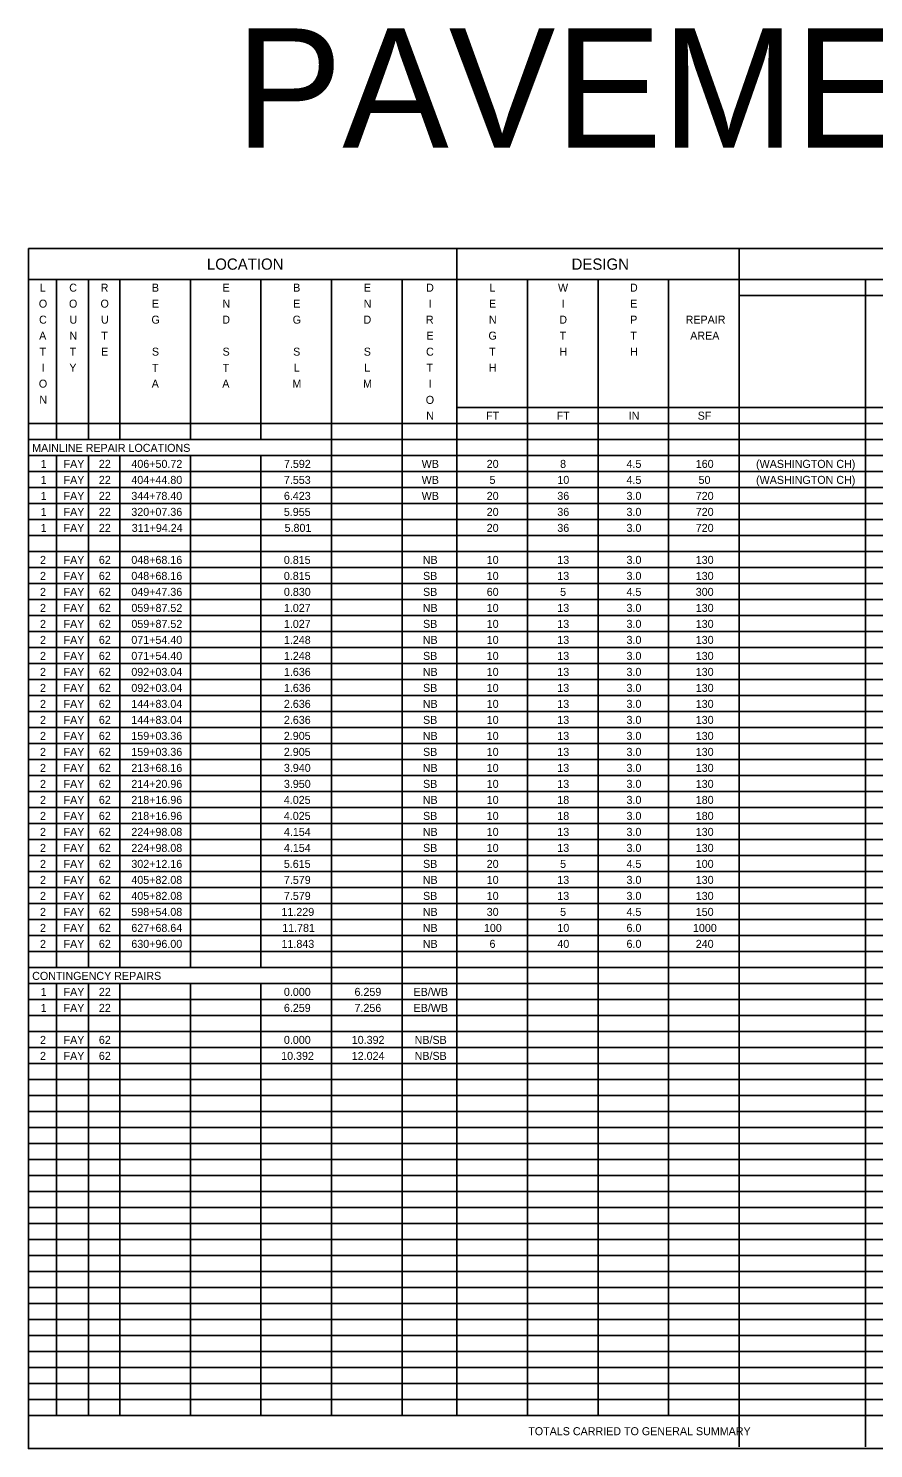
# Model space of a CAD drawing. Extents: x 12522 to 13018, y 1124 to 1902.
# Drawn here: x 12797.22 to 12812.01, y 1864.19 to 1889.04 of the extents above; entities that cross this region are included whole.
import ezdxf

# ---------------------------------------------------------------- set-up
doc = ezdxf.new("R2010")
doc.units = 0
for name, color, linetype in [('SC_Scratch1', 7, 'Continuous'), ('SH_Data', 7, 'Continuous'), ('SH_Text', 7, 'Continuous')]:
    doc.layers.add(name, color=color, linetype=linetype)

msp = doc.modelspace()

# ---------------------------------------------------------------- linework, layer by layer
at = {"layer": 'SC_Scratch1'}
msp.add_lwpolyline([(12797.224, 1885.19), (12827.724, 1885.19), (12827.724, 1864.19), (12797.224, 1864.19)], close=True, dxfattribs=at)
at = {"layer": 'SH_Data'}
for p, q in [((12804.718, 1885.19), (12804.718, 1864.766)), ((12809.659, 1885.19), (12809.659, 1864.223)), ((12797.224, 1884.646), (12827.728, 1884.646)), ((12797.718, 1884.646), (12797.718, 1881.846)), ((12798.278, 1884.646), (12798.278, 1881.846)), ((12798.822, 1884.646), (12798.822, 1881.846)), ((12800.057, 1884.646), (12800.057, 1881.846)), ((12801.292, 1884.646), (12801.292, 1881.846)), ((12802.528, 1884.646), (12802.528, 1864.766)), ((12803.763, 1884.646), (12803.763, 1864.766)), ((12805.954, 1884.646), (12805.954, 1864.766)), ((12807.189, 1884.646), (12807.189, 1864.766)), ((12808.424, 1884.646), (12808.424, 1864.766)), ((12811.867, 1884.646), (12811.867, 1864.223)), ((12809.659, 1884.366), (12820.695, 1884.366)), ((12804.718, 1882.406), (12820.695, 1882.406)), ((12797.224, 1882.126), (12827.728, 1882.126)), ((12797.224, 1881.846), (12827.728, 1881.846)), ((12797.224, 1881.566), (12827.728, 1881.566)), ((12797.718, 1881.566), (12797.718, 1872.606)), ((12798.278, 1881.566), (12798.278, 1872.606)), ((12798.822, 1881.566), (12798.822, 1872.606)), ((12800.057, 1881.566), (12800.057, 1872.606)), ((12801.292, 1881.566), (12801.292, 1872.606)), ((12797.224, 1881.286), (12827.728, 1881.286)), ((12797.224, 1881.006), (12827.728, 1881.006)), ((12797.224, 1880.726), (12827.728, 1880.726)), ((12797.224, 1880.446), (12827.728, 1880.446)), ((12797.224, 1880.166), (12827.728, 1880.166)), ((12797.224, 1879.886), (12827.728, 1879.886)), ((12797.224, 1879.606), (12827.728, 1879.606)), ((12797.224, 1879.326), (12827.728, 1879.326)), ((12797.224, 1879.046), (12827.728, 1879.046)), ((12797.224, 1878.766), (12827.728, 1878.766)), ((12797.224, 1878.486), (12827.728, 1878.486)), ((12797.224, 1878.206), (12827.728, 1878.206)), ((12797.224, 1877.926), (12827.728, 1877.926)), ((12797.224, 1877.646), (12827.728, 1877.646)), ((12797.224, 1877.366), (12827.728, 1877.366)), ((12797.224, 1877.086), (12827.728, 1877.086)), ((12797.224, 1876.806), (12827.728, 1876.806)), ((12797.224, 1876.526), (12827.728, 1876.526)), ((12797.224, 1876.246), (12827.728, 1876.246)), ((12797.224, 1875.966), (12827.728, 1875.966)), ((12797.224, 1875.686), (12827.728, 1875.686)), ((12797.224, 1875.406), (12827.728, 1875.406)), ((12797.224, 1875.126), (12827.728, 1875.126)), ((12797.224, 1874.846), (12827.728, 1874.846)), ((12797.224, 1874.566), (12827.728, 1874.566)), ((12797.224, 1874.286), (12827.728, 1874.286)), ((12797.224, 1874.006), (12827.728, 1874.006)), ((12797.224, 1873.726), (12827.728, 1873.726)), ((12797.224, 1873.446), (12827.728, 1873.446)), ((12797.224, 1873.166), (12827.728, 1873.166)), ((12797.224, 1872.886), (12827.728, 1872.886)), ((12797.224, 1872.606), (12827.728, 1872.606)), ((12797.224, 1872.326), (12827.728, 1872.326)), ((12797.718, 1872.326), (12797.718, 1864.766)), ((12798.278, 1872.326), (12798.278, 1864.766)), ((12798.822, 1872.326), (12798.822, 1864.766)), ((12800.057, 1872.326), (12800.057, 1864.766)), ((12801.292, 1872.326), (12801.292, 1864.766)), ((12797.224, 1872.046), (12827.728, 1872.046)), ((12797.224, 1871.766), (12827.728, 1871.766)), ((12797.224, 1871.486), (12827.728, 1871.486)), ((12797.224, 1871.206), (12827.728, 1871.206)), ((12797.224, 1870.926), (12827.728, 1870.926)), ((12797.224, 1870.646), (12827.728, 1870.646)), ((12797.224, 1870.366), (12827.728, 1870.366)), ((12797.224, 1870.086), (12827.728, 1870.086)), ((12797.224, 1869.806), (12827.728, 1869.806)), ((12797.224, 1869.526), (12827.728, 1869.526)), ((12797.224, 1869.246), (12827.728, 1869.246)), ((12797.224, 1868.966), (12827.728, 1868.966)), ((12797.224, 1868.686), (12827.728, 1868.686)), ((12797.224, 1868.406), (12827.728, 1868.406)), ((12797.224, 1868.126), (12827.728, 1868.126)), ((12797.224, 1867.846), (12827.728, 1867.846)), ((12797.224, 1867.566), (12827.728, 1867.566)), ((12797.224, 1867.286), (12827.728, 1867.286)), ((12797.224, 1867.006), (12827.728, 1867.006)), ((12797.224, 1866.726), (12827.728, 1866.726)), ((12797.224, 1866.446), (12827.728, 1866.446)), ((12797.224, 1866.166), (12827.728, 1866.166)), ((12797.224, 1865.886), (12827.728, 1865.886)), ((12797.224, 1865.606), (12827.728, 1865.606)), ((12797.224, 1865.326), (12827.728, 1865.326)), ((12797.224, 1865.046), (12827.728, 1865.046)), ((12797.224, 1864.766), (12827.728, 1864.766))]:
    msp.add_line(p, q, dxfattribs=at)

# ---------------------------------------------------------------- texts
at = {"layer": 'SC_Scratch1'}
msp.add_text('PAVEMENT REPAIR', height=2.08957, dxfattribs=at).set_placement((12800.851, 1886.953))
at = {"layer": 'SH_Text'}
for s, height, p in [('LOCATION', 0.196, (12800.347, 1884.82)), ('DESIGN', 0.196, (12806.726, 1884.82)), ('L', 0.14, (12797.425, 1884.436)), ('C', 0.14, (12797.938, 1884.436)), ('R', 0.14, (12798.488, 1884.436)), ('B', 0.14, (12799.385, 1884.436)), ('E', 0.14, (12800.621, 1884.436)), ('B', 0.14, (12801.856, 1884.436)), ('E', 0.14, (12803.091, 1884.436)), ('D', 0.14, (12804.182, 1884.436)), ('L', 0.14, (12805.29, 1884.436)), ('W', 0.14, (12806.489, 1884.436)), ('D', 0.14, (12807.748, 1884.436)), ('O', 0.14, (12797.407, 1884.156)), ('O', 0.14, (12797.934, 1884.156)), ('O', 0.14, (12798.486, 1884.156)), ('E', 0.14, (12799.385, 1884.156)), ('N', 0.14, (12800.618, 1884.156)), ('E', 0.14, (12801.856, 1884.156)), ('N', 0.14, (12803.089, 1884.156)), ('I', 0.14, (12804.224, 1884.156)), ('E', 0.14, (12805.282, 1884.156)), ('I', 0.14, (12806.555, 1884.156)), ('E', 0.14, (12807.753, 1884.156)), ('C', 0.14, (12797.411, 1883.876)), ('U', 0.14, (12797.942, 1883.876)), ('U', 0.14, (12798.494, 1883.876)), ('G', 0.14, (12799.377, 1883.876)), ('D', 0.14, (12800.616, 1883.876)), ('G', 0.14, (12801.847, 1883.876)), ('D', 0.14, (12803.087, 1883.876)), ('R', 0.14, (12804.178, 1883.876)), ('N', 0.14, (12805.28, 1883.876)), ('D', 0.14, (12806.512, 1883.876)), ('P', 0.14, (12807.752, 1883.876)), ('REPAIR', 0.14, (12808.722, 1883.876)), ('A', 0.14, (12797.412, 1883.596)), ('N', 0.14, (12797.942, 1883.596)), ('T', 0.14, (12798.498, 1883.596)), ('E', 0.14, (12804.187, 1883.596)), ('G', 0.14, (12805.273, 1883.596)), ('T', 0.14, (12806.519, 1883.596)), ('T', 0.14, (12807.755, 1883.596)), ('AREA', 0.14, (12808.802, 1883.596)), ('T', 0.14, (12797.419, 1883.316)), ('T', 0.14, (12797.946, 1883.316)), ('E', 0.14, (12798.496, 1883.316)), ('S', 0.14, (12799.385, 1883.316)), ('S', 0.14, (12800.621, 1883.316)), ('S', 0.14, (12801.856, 1883.316)), ('S', 0.14, (12803.091, 1883.316)), ('C', 0.14, (12804.181, 1883.316)), ('T', 0.14, (12805.284, 1883.316)), ('H', 0.14, (12806.515, 1883.316)), ('H', 0.14, (12807.75, 1883.316)), ('I', 0.14, (12797.455, 1883.036)), ('Y', 0.14, (12797.94, 1883.036)), ('T', 0.14, (12799.387, 1883.032)), ('T', 0.14, (12800.623, 1883.032)), ('L', 0.14, (12801.864, 1883.036)), ('L', 0.14, (12803.1, 1883.036)), ('T', 0.14, (12804.189, 1883.036)), ('H', 0.14, (12805.279, 1883.036)), ('O', 0.14, (12797.407, 1882.756)), ('A', 0.14, (12799.381, 1882.756)), ('A', 0.14, (12800.616, 1882.756)), ('M', 0.14, (12801.843, 1882.756)), ('M', 0.14, (12803.079, 1882.756)), ('I', 0.14, (12804.224, 1882.756)), ('N', 0.14, (12797.415, 1882.476)), ('O', 0.14, (12804.176, 1882.472)), ('N', 0.14, (12804.184, 1882.196)), ('FT', 0.14, (12805.23, 1882.196)), ('FT', 0.14, (12806.465, 1882.196)), ('IN', 0.14, (12807.726, 1882.196)), ('SF', 0.14, (12808.933, 1882.196)), ('MAINLINE REPAIR LOCATIONS', 0.14, (12797.29, 1881.632)), ('1', 0.14, (12797.439, 1881.352)), ('FAY', 0.14, (12797.839, 1881.352)), ('22', 0.14, (12798.457, 1881.352)), ('406+50.72', 0.14, (12799.026, 1881.352)), ('7.592', 0.14, (12801.695, 1881.352)), ('WB', 0.14, (12804.104, 1881.352)), ('20', 0.14, (12805.242, 1881.352)), ('8', 0.14, (12806.526, 1881.352)), ('4.5', 0.14, (12807.688, 1881.352)), ('160', 0.14, (12808.899, 1881.352)), ('(WASHINGTON CH)', 0.14, (12809.954, 1881.352)), ('1', 0.14, (12797.439, 1881.072)), ('FAY', 0.14, (12797.839, 1881.072)), ('22', 0.14, (12798.457, 1881.072)), ('404+44.80', 0.14, (12799.025, 1881.072)), ('7.553', 0.14, (12801.694, 1881.072)), ('WB', 0.14, (12804.104, 1881.072)), ('5', 0.14, (12805.291, 1881.072)), ('10', 0.14, (12806.478, 1881.072)), ('4.5', 0.14, (12807.688, 1881.072)), ('50', 0.14, (12808.948, 1881.072)), ('(WASHINGTON CH)', 0.14, (12809.954, 1881.072)), ('1', 0.14, (12797.439, 1880.792)), ('FAY', 0.14, (12797.839, 1880.792)), ('22', 0.14, (12798.457, 1880.792)), ('344+78.40', 0.14, (12799.025, 1880.792)), ('6.423', 0.14, (12801.694, 1880.792)), ('WB', 0.14, (12804.104, 1880.792)), ('20', 0.14, (12805.242, 1880.792)), ('36', 0.14, (12806.477, 1880.792)), ('3.0', 0.14, (12807.688, 1880.792)), ('720', 0.14, (12808.899, 1880.792)), ('1', 0.14, (12797.439, 1880.512)), ('FAY', 0.14, (12797.839, 1880.512)), ('22', 0.14, (12798.457, 1880.512)), ('320+07.36', 0.14, (12799.025, 1880.512)), ('5.955', 0.14, (12801.693, 1880.512)), ('20', 0.14, (12805.242, 1880.512)), ('36', 0.14, (12806.477, 1880.512)), ('3.0', 0.14, (12807.688, 1880.512)), ('720', 0.14, (12808.899, 1880.512)), ('1', 0.14, (12797.439, 1880.232)), ('FAY', 0.14, (12797.839, 1880.232)), ('22', 0.14, (12798.457, 1880.232)), ('311+94.24', 0.14, (12799.032, 1880.232)), ('5.801', 0.14, (12801.706, 1880.232)), ('20', 0.14, (12805.242, 1880.232)), ('36', 0.14, (12806.477, 1880.232)), ('3.0', 0.14, (12807.688, 1880.232)), ('720', 0.14, (12808.899, 1880.232)), ('2', 0.14, (12797.427, 1879.672)), ('FAY', 0.14, (12797.839, 1879.672)), ('62', 0.14, (12798.457, 1879.672)), ('048+68.16', 0.14, (12799.025, 1879.672)), ('0.815', 0.14, (12801.693, 1879.672)), ('NB', 0.14, (12804.123, 1879.672)), ('10', 0.14, (12805.242, 1879.672)), ('13', 0.14, (12806.477, 1879.672)), ('3.0', 0.14, (12807.688, 1879.672)), ('130', 0.14, (12808.899, 1879.672)), ('2', 0.14, (12797.427, 1879.392)), ('FAY', 0.14, (12797.839, 1879.392)), ('62', 0.14, (12798.457, 1879.392)), ('048+68.16', 0.14, (12799.025, 1879.392)), ('0.815', 0.14, (12801.693, 1879.392)), ('SB', 0.14, (12804.128, 1879.392)), ('10', 0.14, (12805.242, 1879.392)), ('13', 0.14, (12806.477, 1879.392)), ('3.0', 0.14, (12807.688, 1879.392)), ('130', 0.14, (12808.899, 1879.392)), ('2', 0.14, (12797.427, 1879.112)), ('FAY', 0.14, (12797.839, 1879.112)), ('62', 0.14, (12798.457, 1879.112)), ('049+47.36', 0.14, (12799.025, 1879.112)), ('0.830', 0.14, (12801.694, 1879.112)), ('SB', 0.14, (12804.128, 1879.112)), ('60', 0.14, (12805.242, 1879.112)), ('5', 0.14, (12806.526, 1879.112)), ('4.5', 0.14, (12807.688, 1879.112)), ('300', 0.14, (12808.899, 1879.112)), ('2', 0.14, (12797.427, 1878.832)), ('FAY', 0.14, (12797.839, 1878.832)), ('62', 0.14, (12798.457, 1878.832)), ('059+87.52', 0.14, (12799.026, 1878.832)), ('1.027', 0.14, (12801.694, 1878.832)), ('NB', 0.14, (12804.123, 1878.832)), ('10', 0.14, (12805.242, 1878.832)), ('13', 0.14, (12806.477, 1878.832)), ('3.0', 0.14, (12807.688, 1878.832)), ('130', 0.14, (12808.899, 1878.832)), ('2', 0.14, (12797.427, 1878.552)), ('FAY', 0.14, (12797.839, 1878.552)), ('62', 0.14, (12798.457, 1878.552)), ('059+87.52', 0.14, (12799.026, 1878.552)), ('1.027', 0.14, (12801.694, 1878.552)), ('SB', 0.14, (12804.128, 1878.552)), ('10', 0.14, (12805.242, 1878.552)), ('13', 0.14, (12806.477, 1878.552)), ('3.0', 0.14, (12807.688, 1878.552)), ('130', 0.14, (12808.899, 1878.552)), ('2', 0.14, (12797.427, 1878.272)), ('FAY', 0.14, (12797.839, 1878.272)), ('62', 0.14, (12798.457, 1878.272)), ('071+54.40', 0.14, (12799.025, 1878.272)), ('1.248', 0.14, (12801.694, 1878.272)), ('NB', 0.14, (12804.123, 1878.272)), ('10', 0.14, (12805.242, 1878.272)), ('13', 0.14, (12806.477, 1878.272)), ('3.0', 0.14, (12807.688, 1878.272)), ('130', 0.14, (12808.899, 1878.272)), ('2', 0.14, (12797.427, 1877.992)), ('FAY', 0.14, (12797.839, 1877.992)), ('62', 0.14, (12798.457, 1877.992)), ('071+54.40', 0.14, (12799.025, 1877.992)), ('1.248', 0.14, (12801.694, 1877.992)), ('SB', 0.14, (12804.128, 1877.992)), ('10', 0.14, (12805.242, 1877.992)), ('13', 0.14, (12806.477, 1877.992)), ('3.0', 0.14, (12807.688, 1877.992)), ('130', 0.14, (12808.899, 1877.992)), ('2', 0.14, (12797.427, 1877.712)), ('FAY', 0.14, (12797.839, 1877.712)), ('62', 0.14, (12798.457, 1877.712)), ('092+03.04', 0.14, (12799.025, 1877.712)), ('1.636', 0.14, (12801.694, 1877.712)), ('NB', 0.14, (12804.123, 1877.712)), ('10', 0.14, (12805.242, 1877.712)), ('13', 0.14, (12806.477, 1877.712)), ('3.0', 0.14, (12807.688, 1877.712)), ('130', 0.14, (12808.899, 1877.712)), ('2', 0.14, (12797.427, 1877.432)), ('FAY', 0.14, (12797.839, 1877.432)), ('62', 0.14, (12798.457, 1877.432)), ('092+03.04', 0.14, (12799.025, 1877.432)), ('1.636', 0.14, (12801.694, 1877.432)), ('SB', 0.14, (12804.128, 1877.432)), ('10', 0.14, (12805.242, 1877.432)), ('13', 0.14, (12806.477, 1877.432)), ('3.0', 0.14, (12807.688, 1877.432)), ('130', 0.14, (12808.899, 1877.432)), ('2', 0.14, (12797.427, 1877.152)), ('FAY', 0.14, (12797.839, 1877.152)), ('62', 0.14, (12798.457, 1877.152)), ('144+83.04', 0.14, (12799.025, 1877.152)), ('2.636', 0.14, (12801.694, 1877.152)), ('NB', 0.14, (12804.123, 1877.152)), ('10', 0.14, (12805.242, 1877.152)), ('13', 0.14, (12806.477, 1877.152)), ('3.0', 0.14, (12807.688, 1877.152)), ('130', 0.14, (12808.899, 1877.152)), ('2', 0.14, (12797.427, 1876.872)), ('FAY', 0.14, (12797.839, 1876.872)), ('62', 0.14, (12798.457, 1876.872)), ('144+83.04', 0.14, (12799.025, 1876.872)), ('2.636', 0.14, (12801.694, 1876.872)), ('SB', 0.14, (12804.128, 1876.872)), ('10', 0.14, (12805.242, 1876.872)), ('13', 0.14, (12806.477, 1876.872)), ('3.0', 0.14, (12807.688, 1876.872)), ('130', 0.14, (12808.899, 1876.872)), ('2', 0.14, (12797.427, 1876.592)), ('FAY', 0.14, (12797.839, 1876.592)), ('62', 0.14, (12798.457, 1876.592)), ('159+03.36', 0.14, (12799.025, 1876.592)), ('2.905', 0.14, (12801.693, 1876.592)), ('NB', 0.14, (12804.123, 1876.592)), ('10', 0.14, (12805.242, 1876.592)), ('13', 0.14, (12806.477, 1876.592)), ('3.0', 0.14, (12807.688, 1876.592)), ('130', 0.14, (12808.899, 1876.592)), ('2', 0.14, (12797.427, 1876.312)), ('FAY', 0.14, (12797.839, 1876.312)), ('62', 0.14, (12798.457, 1876.312)), ('159+03.36', 0.14, (12799.025, 1876.312)), ('2.905', 0.14, (12801.693, 1876.312)), ('SB', 0.14, (12804.128, 1876.312)), ('10', 0.14, (12805.242, 1876.312)), ('13', 0.14, (12806.477, 1876.312)), ('3.0', 0.14, (12807.688, 1876.312)), ('130', 0.14, (12808.899, 1876.312)), ('2', 0.14, (12797.427, 1876.032)), ('FAY', 0.14, (12797.839, 1876.032)), ('62', 0.14, (12798.457, 1876.032)), ('213+68.16', 0.14, (12799.025, 1876.032)), ('3.940', 0.14, (12801.694, 1876.032)), ('NB', 0.14, (12804.123, 1876.032)), ('10', 0.14, (12805.242, 1876.032)), ('13', 0.14, (12806.477, 1876.032)), ('3.0', 0.14, (12807.688, 1876.032)), ('130', 0.14, (12808.899, 1876.032)), ('2', 0.14, (12797.427, 1875.752)), ('FAY', 0.14, (12797.839, 1875.752)), ('62', 0.14, (12798.457, 1875.752)), ('214+20.96', 0.14, (12799.025, 1875.752)), ('3.950', 0.14, (12801.694, 1875.752)), ('SB', 0.14, (12804.128, 1875.752)), ('10', 0.14, (12805.242, 1875.752)), ('13', 0.14, (12806.477, 1875.752)), ('3.0', 0.14, (12807.688, 1875.752)), ('130', 0.14, (12808.899, 1875.752)), ('2', 0.14, (12797.427, 1875.472)), ('FAY', 0.14, (12797.839, 1875.472)), ('62', 0.14, (12798.457, 1875.472)), ('218+16.96', 0.14, (12799.025, 1875.472)), ('4.025', 0.14, (12801.693, 1875.472)), ('NB', 0.14, (12804.123, 1875.472)), ('10', 0.14, (12805.242, 1875.472)), ('18', 0.14, (12806.477, 1875.472)), ('3.0', 0.14, (12807.688, 1875.472)), ('180', 0.14, (12808.899, 1875.472)), ('2', 0.14, (12797.427, 1875.192)), ('FAY', 0.14, (12797.839, 1875.192)), ('62', 0.14, (12798.457, 1875.192)), ('218+16.96', 0.14, (12799.025, 1875.192)), ('4.025', 0.14, (12801.693, 1875.192)), ('SB', 0.14, (12804.128, 1875.192)), ('10', 0.14, (12805.242, 1875.192)), ('18', 0.14, (12806.477, 1875.192)), ('3.0', 0.14, (12807.688, 1875.192)), ('180', 0.14, (12808.899, 1875.192)), ('2', 0.14, (12797.427, 1874.912)), ('FAY', 0.14, (12797.839, 1874.912)), ('62', 0.14, (12798.457, 1874.912)), ('224+98.08', 0.14, (12799.025, 1874.912)), ('4.154', 0.14, (12801.694, 1874.912)), ('NB', 0.14, (12804.123, 1874.912)), ('10', 0.14, (12805.242, 1874.912)), ('13', 0.14, (12806.477, 1874.912)), ('3.0', 0.14, (12807.688, 1874.912)), ('130', 0.14, (12808.899, 1874.912)), ('2', 0.14, (12797.427, 1874.632)), ('FAY', 0.14, (12797.839, 1874.632)), ('62', 0.14, (12798.457, 1874.632)), ('224+98.08', 0.14, (12799.025, 1874.632)), ('4.154', 0.14, (12801.694, 1874.632)), ('SB', 0.14, (12804.128, 1874.632)), ('10', 0.14, (12805.242, 1874.632)), ('13', 0.14, (12806.477, 1874.632)), ('3.0', 0.14, (12807.688, 1874.632)), ('130', 0.14, (12808.899, 1874.632)), ('2', 0.14, (12797.427, 1874.352)), ('FAY', 0.14, (12797.839, 1874.352)), ('62', 0.14, (12798.457, 1874.352)), ('302+12.16', 0.14, (12799.025, 1874.352)), ('5.615', 0.14, (12801.693, 1874.352)), ('SB', 0.14, (12804.128, 1874.352)), ('20', 0.14, (12805.242, 1874.352)), ('5', 0.14, (12806.526, 1874.352)), ('4.5', 0.14, (12807.688, 1874.352)), ('100', 0.14, (12808.899, 1874.352)), ('2', 0.14, (12797.427, 1874.072)), ('FAY', 0.14, (12797.839, 1874.072)), ('62', 0.14, (12798.457, 1874.072)), ('405+82.08', 0.14, (12799.025, 1874.072)), ('7.579', 0.14, (12801.694, 1874.072)), ('NB', 0.14, (12804.123, 1874.072)), ('10', 0.14, (12805.242, 1874.072)), ('13', 0.14, (12806.477, 1874.072)), ('3.0', 0.14, (12807.688, 1874.072)), ('130', 0.14, (12808.899, 1874.072)), ('2', 0.14, (12797.427, 1873.792)), ('62', 0.14, (12798.457, 1873.792)), ('405+82.08', 0.14, (12799.025, 1873.792)), ('7.579', 0.14, (12801.694, 1873.792)), ('SB', 0.14, (12804.128, 1873.792)), ('10', 0.14, (12805.242, 1873.792)), ('13', 0.14, (12806.477, 1873.792)), ('3.0', 0.14, (12807.688, 1873.792)), ('130', 0.14, (12808.899, 1873.792)), ('FAY', 0.14, (12797.839, 1873.792)), ('2', 0.14, (12797.427, 1873.512)), ('FAY', 0.14, (12797.839, 1873.512)), ('62', 0.14, (12798.457, 1873.512)), ('598+54.08', 0.14, (12799.025, 1873.512)), ('11.229', 0.14, (12801.651, 1873.512)), ('NB', 0.14, (12804.123, 1873.512)), ('30', 0.14, (12805.242, 1873.512)), ('5', 0.14, (12806.526, 1873.512)), ('4.5', 0.14, (12807.688, 1873.512)), ('150', 0.14, (12808.899, 1873.512)), ('2', 0.14, (12797.427, 1873.232)), ('FAY', 0.14, (12797.839, 1873.232)), ('62', 0.14, (12798.457, 1873.232)), ('627+68.64', 0.14, (12799.025, 1873.232)), ('11.781', 0.14, (12801.664, 1873.232)), ('NB', 0.14, (12804.123, 1873.232)), ('100', 0.14, (12805.193, 1873.232)), ('10', 0.14, (12806.478, 1873.232)), ('6.0', 0.14, (12807.688, 1873.232)), ('1000', 0.14, (12808.85, 1873.232)), ('2', 0.14, (12797.427, 1872.952)), ('FAY', 0.14, (12797.839, 1872.952)), ('62', 0.14, (12798.457, 1872.952)), ('630+96.00', 0.14, (12799.025, 1872.952)), ('11.843', 0.14, (12801.652, 1872.952)), ('NB', 0.14, (12804.123, 1872.952)), ('6', 0.14, (12805.291, 1872.952)), ('40', 0.14, (12806.478, 1872.952)), ('6.0', 0.14, (12807.688, 1872.952)), ('240', 0.14, (12808.899, 1872.952)), ('CONTINGENCY REPAIRS', 0.14, (12797.29, 1872.392)), ('1', 0.14, (12797.439, 1872.112)), ('FAY', 0.14, (12797.839, 1872.112)), ('22', 0.14, (12798.457, 1872.112)), ('0.000', 0.14, (12801.694, 1872.112)), ('6.259', 0.14, (12802.929, 1872.112)), ('EB/WB', 0.14, (12803.962, 1872.112)), ('1', 0.14, (12797.439, 1871.832)), ('FAY', 0.14, (12797.839, 1871.832)), ('22', 0.14, (12798.457, 1871.832)), ('6.259', 0.14, (12801.694, 1871.832)), ('7.256', 0.14, (12802.929, 1871.832)), ('EB/WB', 0.14, (12803.962, 1871.832)), ('2', 0.14, (12797.427, 1871.272)), ('FAY', 0.14, (12797.839, 1871.272)), ('62', 0.14, (12798.457, 1871.272)), ('0.000', 0.14, (12801.694, 1871.272)), ('10.392', 0.14, (12802.881, 1871.272)), ('NB/SB', 0.14, (12803.981, 1871.272)), ('2', 0.14, (12797.427, 1870.992)), ('FAY', 0.14, (12797.839, 1870.992)), ('62', 0.14, (12798.457, 1870.992)), ('10.392', 0.14, (12801.646, 1870.992)), ('12.024', 0.14, (12802.881, 1870.992)), ('NB/SB', 0.14, (12803.981, 1870.992)), ('TOTALS CARRIED TO GENERAL SUMMARY', 0.14, (12805.969, 1864.424))]:
    msp.add_text(s, height=height, dxfattribs=at).set_placement(p)

doc.saveas('drawing.dxf')
